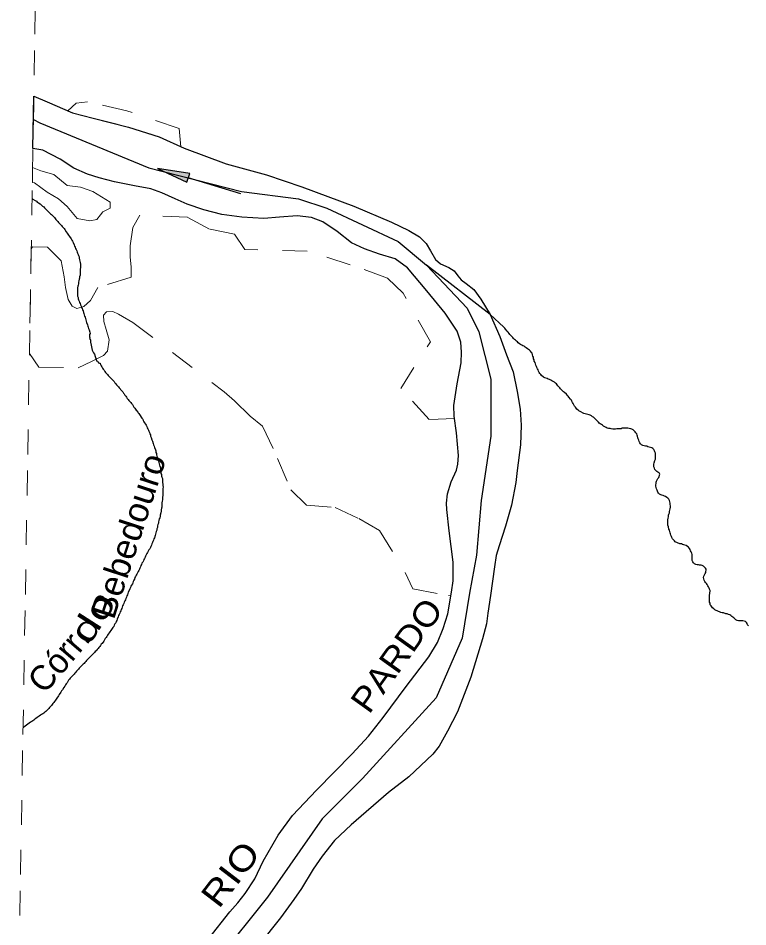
# Model space of a CAD drawing. Extents: x 785.9 to 812.4, y 7674.9 to 7703.1.
# Drawn here: x 786.199 to 789.145, y 7693.236 to 7696.903 of the extents above; entities that cross this region are included whole.
import ezdxf
from ezdxf.enums import TextEntityAlignment as Align

# ---------------------------------------------------------------- set-up
doc = ezdxf.new("R2010")
doc.units = 0
doc.header["$LTSCALE"] = 0.04
doc.linetypes.add('SHORT_DASHED', pattern=[2.7, 1.5, -1.2])
for name, color, linetype, lineweight in [('10', 7, 'Continuous', 25), ('2', 7, 'Continuous', 25), ('21', 7, 'SHORT_DASHED', 13), ('53', 7, 'SHORT_DASHED', 13), ('55', 7, 'Continuous', 25), ('7', 7, 'Continuous', 25)]:
    doc.layers.add(name, color=color, linetype=linetype, lineweight=lineweight)
doc.layers.add('61', color=7, linetype='Continuous')

msp = doc.modelspace()

# ---------------------------------------------------------------- hatches: boundary and pattern name
at = {"layer": '10'}
msp.add_hatch(color=256, dxfattribs=at).paths.add_polyline_path([(786.7608, 7696.2965), (786.8803, 7696.241), (786.8911, 7696.2763)])

# ---------------------------------------------------------------- linework, layer by layer
msp.add_line((787.0983, 7696.1942), (786.8857, 7696.2586), dxfattribs=at)
msp.add_lwpolyline([(786.7608, 7696.2965), (786.8803, 7696.241), (786.8911, 7696.2763)], close=True, dxfattribs=at)
at = {"layer": '2'}
for points in [[(787.4871, 7696.0426), (787.4289, 7696.0814), (787.3826, 7696.0986), (787.3255, 7696.1062), (787.2533, 7696.1008), (787.1908, 7696.0943), (787.1014, 7696.1008), (787.0206, 7696.1116), (786.9484, 7696.1299), (786.8805, 7696.1525), (786.832, 7696.1741), (786.7792, 7696.1978), (786.734, 7696.214), (786.6683, 7696.2269), (786.5875, 7696.2431), (786.525, 7696.2592), (786.4787, 7696.2732), (786.4237, 7696.298), (786.3677, 7696.3346), (786.2988, 7696.3702), (786.2583, 7696.3768), (786.2619, 7696.5891)], [(786.2619, 7696.5891), (786.3157, 7696.5656), (786.4181, 7696.5214), (786.501, 7696.4999), (786.6443, 7696.4633), (786.7682, 7696.4245), (786.8684, 7696.3781), (787.0386, 7696.3156), (787.2013, 7696.2704), (787.3445, 7696.223), (787.5546, 7696.1443), (787.7055, 7696.0807), (787.7766, 7696.0462), (787.8197, 7696.0215), (787.8455, 7695.9945), (787.8638, 7695.9643), (787.8843, 7695.9288), (787.9037, 7695.9115), (787.9382, 7695.8975), (787.9586, 7695.8835), (787.9737, 7695.8641), (787.9877, 7695.8469), (788.0071, 7695.8329), (788.0384, 7695.8081), (788.0674, 7695.7693), (788.1051, 7695.7068), (788.1439, 7695.6184), (788.1698, 7695.5452), (788.1967, 7695.4762), (788.214, 7695.3965), (788.2258, 7695.3253), (788.229, 7695.2607), (788.2269, 7695.181), (788.2129, 7695.0775), (788.2075, 7695.029), (788.1903, 7694.9385), (788.1666, 7694.8534), (788.1407, 7694.7737), (788.1288, 7694.7349), (788.1224, 7694.6885), (788.1062, 7694.5732), (788.0954, 7694.5021), (788.089, 7694.459), (788.0739, 7694.3987), (788.0265, 7694.2435), (787.9727, 7694.1045), (787.9328, 7694.0259), (787.8984, 7693.9655), (787.8725, 7693.9332), (787.7766, 7693.8416), (787.6936, 7693.778), (787.5428, 7693.6476), (787.476, 7693.5852), (787.4265, 7693.5216), (787.3898, 7693.4688), (787.3424, 7693.3912), (787.3123, 7693.347), (787.2573, 7693.2727), (787.1733, 7693.166)], [(786.9688, 7693.1893), (787.0529, 7693.2971), (787.0852, 7693.3337), (787.1153, 7693.3703), (787.1541, 7693.4296), (787.1875, 7693.5007), (787.2478, 7693.6063), (787.306, 7693.685), (787.4029, 7693.7874), (787.5473, 7693.9339), (787.6131, 7694.0061), (787.6723, 7694.0815), (787.765, 7694.2065), (787.8565, 7694.3261), (787.8921, 7694.3832), (787.9147, 7694.4403), (787.933, 7694.4996), (787.9481, 7694.5869), (787.9546, 7694.6321), (787.9546, 7694.7076), (787.9395, 7694.8347), (787.9298, 7694.9209), (787.9287, 7694.9467), (787.932, 7694.9834), (787.947, 7695.0319), (787.9686, 7695.0793), (787.974, 7695.104), (787.9772, 7695.1385), (787.9686, 7695.2301), (787.9589, 7695.297), (787.9579, 7695.3401), (787.9708, 7695.4273), (787.988, 7695.5125), (787.9891, 7695.5556), (787.9859, 7695.5954), (787.9718, 7695.6396), (787.9223, 7695.7129), (787.849, 7695.8034), (787.7704, 7695.896), (787.7208, 7695.9327), (787.6573, 7695.951), (787.5969, 7695.9725), (787.5442, 7695.9973), (787.4871, 7696.0426)]]:
    msp.add_lwpolyline(points, dxfattribs=at)
at = {"layer": '21'}
msp.add_line((786.2513, 7695.9719), (786.2441, 7695.5504), dxfattribs=at)
for points in [[(786.478, 7696.566), (786.4327, 7696.56), (786.3993, 7696.5295)], [(786.3993, 7696.5295), (786.4181, 7696.5214), (786.501, 7696.4999), (786.6443, 7696.4633), (786.7682, 7696.4245), (786.8549, 7696.3844)], [(786.8549, 7696.3844), (786.8486, 7696.4584), (786.637, 7696.5293), (786.478, 7696.566)], [(786.257, 7696.3011), (786.2565, 7696.2732), (786.2559, 7696.2402), (786.264, 7696.2388), (786.3157, 7696.2009)], [(786.3157, 7696.2009), (786.3619, 7696.1741), (786.397, 7696.1436), (786.4367, 7696.0955), (786.4875, 7696.0854), (786.5162, 7696.0909), (786.5309, 7696.1103), (786.5411, 7696.1223), (786.5697, 7696.1371), (786.5707, 7696.1612), (786.5005, 7696.2037), (786.4506, 7696.2212), (786.397, 7696.2286), (786.3425, 7696.2721), (786.2908, 7696.2878), (786.257, 7696.3011)], [(787.9602, 7695.2883), (787.8583, 7695.2835), (787.7432, 7695.4085), (787.8632, 7695.5973), (787.753, 7695.7933), (787.6893, 7695.8546), (787.5398, 7695.9085), (787.3659, 7695.9625), (787.1136, 7695.9698), (787.0719, 7696.0311), (786.9716, 7696.0523), (786.8825, 7696.0996), (786.6899, 7696.1077), (786.661, 7696.0579), (786.6514, 7695.9849), (786.6514, 7695.9383), (786.6546, 7695.8994), (786.6546, 7695.8577), (786.5206, 7695.8159), (786.5206, 7695.8159)], [(786.5206, 7695.8159), (786.4901, 7695.7645), (786.4644, 7695.7396), (786.4355, 7695.7316), (786.4162, 7695.7404), (786.4002, 7695.7677), (786.3898, 7695.8158), (786.3841, 7695.8592), (786.372, 7695.9238), (786.3167, 7695.979), (786.2566, 7695.9801), (786.2513, 7695.9719)], [(786.2441, 7695.5504), (786.2822, 7695.4948), (786.4403, 7695.4924), (786.4941, 7695.5181), (786.5438, 7695.5421), (786.5591, 7695.5598), (786.5655, 7695.6047), (786.5543, 7695.6473), (786.5446, 7695.6786), (786.5438, 7695.7043), (786.5551, 7695.7187), (786.5815, 7695.7195), (786.604, 7695.7083), (786.662, 7695.6746)], [(786.662, 7695.6746), (787.0303, 7695.396), (787.0723, 7695.3585), (787.136, 7695.2972), (787.1846, 7695.2563), (787.2463, 7695.1269), (787.2999, 7695.0003), (787.3633, 7694.9377), (787.4788, 7694.9281), (787.5741, 7694.8837), (787.6574, 7694.836), (787.7616, 7694.666), (787.7922, 7694.6007), (787.9358, 7694.5734), (787.9455, 7694.5719)]]:
    msp.add_lwpolyline(points, dxfattribs=at)
at = {"layer": '53'}
msp.add_lwpolyline([(786.1986, 7692.8823), (786.2082, 7693.4474), (786.2179, 7694.0126), (786.2276, 7694.5777), (786.2372, 7695.1429), (786.2468, 7695.708), (786.2565, 7696.2732), (786.2661, 7696.8383), (786.2758, 7697.4034), (786.2854, 7697.9686), (786.2951, 7698.5337), (786.3047, 7699.0989), (786.3143, 7699.664), (786.324, 7700.2291), (786.3336, 7700.7943), (786.3432, 7701.3594), (786.3528, 7701.9246), (786.3625, 7702.4897), (786.3721, 7703.0549)], dxfattribs=at)
at = {"layer": '55'}
for p, q in [((786.2603, 7696.4943), (786.2859, 7696.4815)), ((788.1051, 7695.7068), (787.8479, 7695.9062))]:
    msp.add_line(p, q, dxfattribs=at)
msp.add_lwpolyline([(786.2859, 7696.4815), (786.7267, 7696.2993), (787.1005, 7696.2034), (787.3305, 7696.1747), (787.4455, 7696.1363), (787.5892, 7696.0692), (787.7329, 7696.0021), (787.8479, 7695.9062), (788.0109, 7695.7336), (788.0588, 7695.6377), (788.1067, 7695.4459), (788.1067, 7695.2158), (788.0683, 7694.9569), (788.0492, 7694.7363), (788.0204, 7694.5829), (787.9917, 7694.4007), (787.8863, 7694.161), (787.5892, 7693.835), (787.4263, 7693.672), (787.2059, 7693.3555), (787.0046, 7693.1062)], dxfattribs=at)
at = {"layer": '7'}
for points in [[(786.2548, 7696.1752), (786.2582, 7696.1731), (786.2671, 7696.1674), (786.272, 7696.1642), (786.276, 7696.1609), (786.2801, 7696.1577), (786.2873, 7696.1536), (786.2971, 7696.1447), (786.3019, 7696.1415), (786.3051, 7696.1375), (786.3084, 7696.1334), (786.3132, 7696.1302), (786.3173, 7696.1261), (786.3213, 7696.1221), (786.3294, 7696.114), (786.3335, 7696.1108), (786.3367, 7696.1067), (786.3448, 7696.0986), (786.348, 7696.0946), (786.3513, 7696.0905), (786.3545, 7696.0865), (786.3585, 7696.0833), (786.3618, 7696.0792), (786.3699, 7696.0711), (786.3731, 7696.0671), (786.3764, 7696.063), (786.3844, 7696.0549), (786.3877, 7696.0501), (786.3925, 7696.0404), (786.3958, 7696.0355), (786.4022, 7696.0274), (786.4055, 7696.0226), (786.412, 7696.0129), (786.4152, 7696.008), (786.4176, 7696.0031), (786.4209, 7695.9983), (786.4241, 7695.9886), (786.4265, 7695.9837), (786.4289, 7695.9789), (786.4306, 7695.974), (786.433, 7695.9692), (786.4354, 7695.9643), (786.437, 7695.9595), (786.4387, 7695.9546), (786.4403, 7695.9497), (786.4427, 7695.9449), (786.4443, 7695.94), (786.4451, 7695.9344), (786.4467, 7695.9287), (786.4476, 7695.923), (786.4492, 7695.9174), (786.45, 7695.9109), (786.45, 7695.8996), (786.4492, 7695.8883), (786.4492, 7695.8713), (786.4484, 7695.8656), (786.4467, 7695.8599), (786.4459, 7695.8543), (786.4443, 7695.8494), (786.4435, 7695.8437), (786.4427, 7695.8381), (786.4419, 7695.8316), (786.4411, 7695.8259), (786.4395, 7695.8211), (786.4387, 7695.8154), (786.4378, 7695.8098), (786.4378, 7695.7871), (786.4387, 7695.7814), (786.4403, 7695.7766), (786.4411, 7695.7709), (786.4427, 7695.7661), (786.4451, 7695.7612), (786.4467, 7695.7564), (786.4492, 7695.7515), (786.4508, 7695.7467), (786.4524, 7695.741), (786.4548, 7695.7361), (786.4565, 7695.7313), (786.4589, 7695.7264), (786.4613, 7695.7216), (786.4621, 7695.7159), (786.4637, 7695.711), (786.4654, 7695.7062), (786.467, 7695.7013), (786.4686, 7695.6965), (786.4702, 7695.6908), (786.4718, 7695.686), (786.4734, 7695.6811), (786.4751, 7695.6754), (786.4783, 7695.6657), (786.4799, 7695.6609), (786.4815, 7695.656), (786.4832, 7695.6512), (786.4848, 7695.6455), (786.488, 7695.6358), (786.4896, 7695.6309), (786.4866, 7695.6266), (786.4866, 7695.6215)], [(788.455, 7695.3251), (788.4518, 7695.3291), (788.4486, 7695.3332), (788.4453, 7695.338), (788.4421, 7695.3429), (788.4397, 7695.3477), (788.4364, 7695.3526), (788.4348, 7695.3575), (788.4324, 7695.3623), (788.4291, 7695.3664), (788.4227, 7695.3744), (788.4194, 7695.3785), (788.4154, 7695.3817), (788.4122, 7695.3858), (788.4041, 7695.3922), (788.4, 7695.3955), (788.396, 7695.3987), (788.3927, 7695.4028), (788.3887, 7695.4068), (788.3855, 7695.4109), (788.3814, 7695.4149), (788.3782, 7695.4189), (788.3717, 7695.427), (788.3677, 7695.4303), (788.3636, 7695.4343), (788.3539, 7695.4392), (788.349, 7695.4424), (788.3442, 7695.4448), (788.3393, 7695.4465), (788.3345, 7695.4489), (788.3248, 7695.4521), (788.3199, 7695.4545), (788.3118, 7695.461), (788.3086, 7695.4659), (788.3053, 7695.4699), (788.3021, 7695.474), (788.2997, 7695.4788), (788.2981, 7695.4837), (788.2956, 7695.4885), (788.2932, 7695.4934), (788.2916, 7695.4982), (788.2892, 7695.5031), (788.2875, 7695.508), (788.2859, 7695.5136), (788.2827, 7695.5185), (788.2819, 7695.5241), (788.2795, 7695.529), (788.2795, 7695.5347), (788.277, 7695.5395), (788.2754, 7695.5452), (788.2738, 7695.5508), (788.2706, 7695.5549), (788.2673, 7695.5589), (788.2633, 7695.563), (788.2592, 7695.5662), (788.2552, 7695.5694), (788.2503, 7695.5727), (788.2463, 7695.5759), (788.2414, 7695.5792), (788.2366, 7695.5816), (788.2317, 7695.584), (788.2269, 7695.5864), (788.2228, 7695.5897), (788.218, 7695.5929), (788.2147, 7695.597), (788.2107, 7695.6002), (788.2066, 7695.6034), (788.2026, 7695.6067), (788.1985, 7695.6107), (788.1953, 7695.6148), (788.1913, 7695.618), (788.188, 7695.622), (788.184, 7695.6261), (788.1807, 7695.6309), (788.1775, 7695.6358), (788.1735, 7695.6398), (788.167, 7695.6479), (788.1637, 7695.652), (788.1597, 7695.656), (788.1051, 7695.7068)], [(786.4866, 7695.6215), (786.4866, 7695.6169), (786.4881, 7695.6134), (786.4866, 7695.6098), (786.4897, 7695.6073), (786.4912, 7695.6042), (786.4912, 7695.5956), (786.4927, 7695.5833), (786.4973, 7695.5635), (786.5029, 7695.5533), (786.5065, 7695.5472), (786.5095, 7695.5375), (786.5131, 7695.5253), (786.5161, 7695.5197), (786.5187, 7695.5187), (786.5207, 7695.5166), (786.5222, 7695.5161), (786.5227, 7695.5126), (786.5273, 7695.511), (786.5293, 7695.5104), (786.5309, 7695.5055), (786.5333, 7695.5007), (786.5358, 7695.4958), (786.539, 7695.491), (786.5422, 7695.4869), (786.5455, 7695.4829), (786.5487, 7695.478), (786.5519, 7695.4732), (786.5552, 7695.4691), (786.5592, 7695.4651), (786.5625, 7695.461), (786.5665, 7695.457), (786.5697, 7695.4529), (786.5778, 7695.4448), (786.5819, 7695.4408), (786.5859, 7695.4367), (786.5892, 7695.4319), (786.5924, 7695.4278), (786.5956, 7695.4238), (786.5997, 7695.4198), (786.6037, 7695.4157), (786.607, 7695.4109), (786.6167, 7695.3987), (786.6207, 7695.3947), (786.6239, 7695.3906), (786.6272, 7695.3866), (786.6288, 7695.3817), (786.6328, 7695.3777), (786.6361, 7695.3736), (786.6385, 7695.3688), (786.6426, 7695.3647), (786.6458, 7695.3607), (786.649, 7695.3558), (786.6531, 7695.3518), (786.6563, 7695.3477), (786.6596, 7695.3437), (786.6628, 7695.3388), (786.666, 7695.334), (786.6693, 7695.3291), (786.6757, 7695.321), (786.6798, 7695.317), (786.6822, 7695.3121), (786.6854, 7695.3081), (786.6887, 7695.304), (786.6984, 7695.2895), (786.7016, 7695.2846), (786.7032, 7695.279), (786.7065, 7695.2749), (786.7089, 7695.2701), (786.7121, 7695.2652), (786.7154, 7695.2604), (786.7178, 7695.2555), (786.7194, 7695.2506), (786.7219, 7695.2458), (786.7243, 7695.2409), (786.7267, 7695.2361), (786.7291, 7695.2312), (786.7308, 7695.2264), (786.7324, 7695.2215), (786.7332, 7695.2159), (786.7356, 7695.211), (786.7388, 7695.2013), (786.7405, 7695.1964), (786.7437, 7695.1867), (786.7453, 7695.1811), (786.7477, 7695.1762), (786.7494, 7695.1713), (786.7526, 7695.1616), (786.7542, 7695.1568), (786.7542, 7695.1511), (786.7566, 7695.1463), (786.7575, 7695.1406), (786.7591, 7695.1357), (786.7607, 7695.1301), (786.7623, 7695.1252), (786.7655, 7695.1155), (786.7664, 7695.1099), (786.768, 7695.105), (786.7696, 7695.0993), (786.7712, 7695.0945), (786.7728, 7695.0896)], [(788.8216, 7694.9658), (788.8175, 7694.9691), (788.8127, 7694.9723), (788.8078, 7694.9739), (788.803, 7694.9763), (788.7981, 7694.978), (788.7933, 7694.9796), (788.7884, 7694.9828), (788.7844, 7694.9861), (788.7811, 7694.9901), (788.7787, 7694.999), (788.7763, 7695.0039), (788.7747, 7695.0087), (788.773, 7695.0144), (788.773, 7695.02), (788.7747, 7695.0249), (788.7747, 7695.0306), (788.7763, 7695.0354), (788.7787, 7695.0403), (788.7819, 7695.0451), (788.786, 7695.0492), (788.79, 7695.0629), (788.7868, 7695.0678), (788.7819, 7695.071), (788.7779, 7695.0743), (788.7738, 7695.0783), (788.7698, 7695.0823), (788.7674, 7695.0872), (788.7658, 7695.0921), (788.7649, 7695.0977), (788.7649, 7695.1034), (788.7666, 7695.109), (788.7698, 7695.1188), (788.7714, 7695.1236), (788.7722, 7695.1366), (788.7714, 7695.1422), (788.7714, 7695.1479), (788.769, 7695.1527), (788.7674, 7695.1576), (788.7649, 7695.1624), (788.7617, 7695.1665), (788.7568, 7695.1689), (788.752, 7695.1705), (788.7471, 7695.1722), (788.7415, 7695.1738), (788.7366, 7695.1754), (788.731, 7695.1762), (788.7261, 7695.1778), (788.7204, 7695.1786), (788.7156, 7695.1819), (788.7115, 7695.1851), (788.7083, 7695.19), (788.7067, 7695.1948), (788.7043, 7695.1997), (788.7026, 7695.2053), (788.701, 7695.2102), (788.6994, 7695.2159), (788.6978, 7695.2207), (788.6962, 7695.2256), (788.6929, 7695.2304), (788.6897, 7695.2345), (788.6856, 7695.2385), (788.6816, 7695.2417), (788.6767, 7695.2442), (788.6719, 7695.2458), (788.6662, 7695.2474), (788.6606, 7695.2482), (788.6379, 7695.2482), (788.6331, 7695.2466), (788.6274, 7695.2466), (788.6217, 7695.2458), (788.6161, 7695.2458), (788.6104, 7695.245), (788.5991, 7695.245), (788.5934, 7695.2458), (788.5885, 7695.2474), (788.5829, 7695.2474), (788.5772, 7695.249), (788.5724, 7695.2515), (788.5675, 7695.2547), (788.5627, 7695.2571), (788.5578, 7695.2604), (788.5538, 7695.2636), (788.5489, 7695.266), (788.5449, 7695.2693), (788.5416, 7695.2733), (788.5376, 7695.2773), (788.5343, 7695.2814), (788.5262, 7695.2895), (788.5222, 7695.2927), (788.5173, 7695.2951), (788.5133, 7695.2984), (788.5084, 7695.3008), (788.5036, 7695.3024), (788.4939, 7695.3057), (788.4882, 7695.3065), (788.4826, 7695.3081), (788.468, 7695.3154), (788.4631, 7695.3186), (788.4591, 7695.3219), (788.455, 7695.3251)], [(786.7728, 7695.0896), (786.7736, 7695.0791), (786.7753, 7695.0662), (786.7769, 7695.0613), (786.7777, 7695.0556), (786.7793, 7695.0508), (786.7809, 7695.0459), (786.7809, 7695.0346), (786.7817, 7695.0289), (786.7833, 7695.0233), (786.7833, 7695.0168), (786.7842, 7695.0111), (786.7833, 7695.0047), (786.7833, 7694.9933), (786.7825, 7694.9877), (786.7825, 7694.9763), (786.7817, 7694.9707), (786.7817, 7694.965), (786.7809, 7694.9594), (786.7801, 7694.9537), (786.7793, 7694.948), (786.7793, 7694.9359), (786.7785, 7694.9302), (786.7769, 7694.9254), (786.7761, 7694.9189), (786.7761, 7694.9132), (786.7753, 7694.9076), (786.772, 7694.8979), (786.772, 7694.8922), (786.7704, 7694.8873), (786.768, 7694.8825), (786.7672, 7694.876), (786.7655, 7694.8712), (786.7647, 7694.8655), (786.7623, 7694.8598), (786.7615, 7694.8542), (786.7607, 7694.8477), (786.7591, 7694.842), (786.7583, 7694.8364), (786.7558, 7694.8315), (786.755, 7694.8258), (786.7534, 7694.821), (786.7518, 7694.8161), (786.7486, 7694.8064), (786.7469, 7694.8016), (786.7445, 7694.7967), (786.7421, 7694.7919), (786.7405, 7694.787), (786.7388, 7694.7813), (786.7364, 7694.7765), (786.7348, 7694.7716), (786.7324, 7694.7668), (786.7299, 7694.7619), (786.7267, 7694.7571), (786.7235, 7694.7522), (786.721, 7694.7474), (786.7186, 7694.7425), (786.7154, 7694.7376), (786.713, 7694.7328), (786.7113, 7694.7279), (786.7089, 7694.7231), (786.7057, 7694.7182), (786.7041, 7694.7134), (786.7016, 7694.7085), (786.6984, 7694.7037), (786.6968, 7694.6988), (786.6943, 7694.694), (786.6919, 7694.6891), (786.6895, 7694.6842), (786.6879, 7694.6794), (786.6854, 7694.6745), (786.683, 7694.6697), (786.6798, 7694.6648), (786.6782, 7694.66), (786.6749, 7694.6551), (786.6725, 7694.6503), (786.6693, 7694.6454), (786.6685, 7694.6397), (786.666, 7694.6349), (786.6628, 7694.63), (786.6612, 7694.6252), (786.6596, 7694.6203), (786.6563, 7694.6155), (786.6539, 7694.6106), (786.6523, 7694.6058), (786.6498, 7694.6009), (786.6482, 7694.596), (786.6434, 7694.5863), (786.6401, 7694.5766), (786.6377, 7694.5718), (786.6361, 7694.5661), (786.6337, 7694.5613), (786.632, 7694.5564), (786.6296, 7694.5515), (786.6264, 7694.5467), (786.6256, 7694.541), (786.6231, 7694.5362), (786.6199, 7694.5313), (786.6167, 7694.5216), (786.6142, 7694.5168), (786.6126, 7694.5119)], [(789.0765, 7694.4925), (789.0716, 7694.4957), (789.0668, 7694.4973), (789.0619, 7694.499), (789.0562, 7694.4998), (789.0465, 7694.503), (789.0409, 7694.5038), (789.036, 7694.5054), (789.0311, 7694.507), (789.0263, 7694.5087), (789.0214, 7694.5111), (789.0166, 7694.5127), (789.0117, 7694.5159), (789.0069, 7694.5192), (789.0028, 7694.5232), (788.9996, 7694.5273), (788.9964, 7694.5313), (788.9931, 7694.5362), (788.9923, 7694.5418), (788.9899, 7694.5467), (788.9899, 7694.5637), (788.9907, 7694.5693), (788.9907, 7694.575), (788.9915, 7694.5815), (788.9923, 7694.5936), (788.9907, 7694.5985), (788.9891, 7694.6033), (788.9866, 7694.6082), (788.9834, 7694.613), (788.981, 7694.6179), (788.9777, 7694.6219), (788.9745, 7694.626), (788.9713, 7694.63), (788.968, 7694.6349), (788.9672, 7694.6406), (788.9664, 7694.6462), (788.9672, 7694.6519), (788.9705, 7694.6567), (788.9729, 7694.6616), (788.9753, 7694.6664), (788.9769, 7694.6794), (788.9737, 7694.6842), (788.9705, 7694.6883), (788.9656, 7694.6915), (788.9608, 7694.694), (788.9559, 7694.6956), (788.9502, 7694.6956), (788.9454, 7694.6972), (788.9397, 7694.6972), (788.9349, 7694.6988), (788.93, 7694.7012), (788.926, 7694.7053), (788.9227, 7694.7093), (788.9203, 7694.7142), (788.9203, 7694.7393), (788.9187, 7694.7441), (788.9163, 7694.749), (788.9138, 7694.7538), (788.9114, 7694.7587), (788.909, 7694.7635), (788.9057, 7694.7684), (788.9009, 7694.7716), (788.896, 7694.7749), (788.8863, 7694.7781), (788.8815, 7694.7797), (788.8766, 7694.7813), (788.8709, 7694.7822), (788.8612, 7694.7854), (788.8515, 7694.7902), (788.8483, 7694.7943), (788.8442, 7694.7983), (788.841, 7694.8024), (788.8378, 7694.8072), (788.8361, 7694.8121), (788.8345, 7694.8169), (788.8329, 7694.8218), (788.8313, 7694.8267), (788.8297, 7694.8315), (788.8281, 7694.8364), (788.8256, 7694.8412), (788.824, 7694.8509), (788.8224, 7694.8566), (788.8216, 7694.8623), (788.8216, 7694.8736), (788.8224, 7694.8792), (788.8232, 7694.8849), (788.824, 7694.8906), (788.8248, 7694.897), (788.8264, 7694.9019), (788.8281, 7694.9068), (788.8281, 7694.9124), (788.8305, 7694.9173), (788.8313, 7694.9229), (788.8321, 7694.9294), (788.8321, 7694.9351), (788.8313, 7694.9407), (788.8313, 7694.9464), (788.8297, 7694.9513), (788.8289, 7694.9569), (788.8256, 7694.9618), (788.8216, 7694.9658)], [(786.6126, 7694.5119), (786.6102, 7694.507), (786.6086, 7694.5022), (786.6061, 7694.4973), (786.6037, 7694.4925), (786.6021, 7694.4876), (786.5989, 7694.4779), (786.5964, 7694.4731), (786.594, 7694.4682), (786.5924, 7694.4633), (786.5892, 7694.4585), (786.5867, 7694.4536), (786.5843, 7694.4488), (786.5811, 7694.4447), (786.5786, 7694.4399), (786.5754, 7694.4358), (786.5722, 7694.4318), (786.5689, 7694.4269), (786.5657, 7694.4221), (786.5625, 7694.4172), (786.5592, 7694.4132), (786.5568, 7694.4083), (786.5536, 7694.4035), (786.5503, 7694.3994), (786.5471, 7694.3946), (786.5447, 7694.3897), (786.5382, 7694.38), (786.5341, 7694.3768), (786.5309, 7694.3719), (786.5277, 7694.3671), (786.5244, 7694.363), (786.5212, 7694.359), (786.5171, 7694.3549), (786.5139, 7694.3501), (786.5099, 7694.3468), (786.5066, 7694.3428), (786.5034, 7694.3387), (786.4993, 7694.3347), (786.4945, 7694.3315), (786.4904, 7694.3274), (786.4872, 7694.3234), (786.4832, 7694.3193), (786.4791, 7694.3153), (786.4751, 7694.3112), (786.4718, 7694.3072), (786.4678, 7694.3031), (786.4645, 7694.2991), (786.4605, 7694.2959), (786.4573, 7694.2918), (786.4532, 7694.2878), (786.4492, 7694.2845), (786.4451, 7694.2805), (786.4419, 7694.2764), (786.4387, 7694.2724), (786.4346, 7694.2683), (786.4314, 7694.2643), (786.4273, 7694.2603), (786.4241, 7694.2562), (786.4209, 7694.2514), (786.4128, 7694.2433), (786.4087, 7694.24), (786.4055, 7694.2352), (786.4022, 7694.2311), (786.3958, 7694.2214), (786.3925, 7694.2174), (786.3901, 7694.2125), (786.3869, 7694.2077), (786.3836, 7694.2028), (786.3772, 7694.1931), (786.3739, 7694.1882), (786.3707, 7694.1834), (786.3642, 7694.1737), (786.3618, 7694.1688), (786.3553, 7694.1591), (786.3521, 7694.1551), (786.3488, 7694.151), (786.3456, 7694.1462), (786.3424, 7694.1421), (786.3391, 7694.1381), (786.3327, 7694.13), (786.3294, 7694.1259), (786.3254, 7694.1219), (786.3221, 7694.1178), (786.31, 7694.1057), (786.306, 7694.1025), (786.3019, 7694.0992), (786.2979, 7694.096), (786.293, 7694.0928), (786.2882, 7694.0903), (786.2833, 7694.0871), (786.2752, 7694.0806), (786.2704, 7694.0774), (786.2663, 7694.0742), (786.2615, 7694.0709), (786.2574, 7694.0677), (786.2534, 7694.0644), (786.2485, 7694.062), (786.2437, 7694.0588), (786.2275, 7694.0466), (786.2197, 7694.0408), (786.2184, 7694.0399)], [(789.1469, 7694.4504), (789.1436, 7694.4553), (789.142, 7694.4601), (789.1396, 7694.465), (789.1355, 7694.4682), (789.1307, 7694.4698), (789.125, 7694.4706), (789.1193, 7694.4706), (789.1129, 7694.4714), (789.1072, 7694.4714), (789.1015, 7694.4731), (789.0967, 7694.4755), (789.0926, 7694.4795), (789.0886, 7694.4828), (789.0846, 7694.486), (789.0805, 7694.4892), (789.0765, 7694.4925)]]:
    msp.add_lwpolyline(points, dxfattribs=at)

# ---------------------------------------------------------------- texts
at = {"layer": '61'}
for s, rotation, width, p in [('Bebedouro', 71.931, 1.05, (786.6911, 7694.7987)), ('do', 57.278, 1.4, (786.5414, 7694.457)), ('PARDO', 54.417, 1.1, (787.7677, 7694.3032)), ('RIO', 52.587, 1.2, (787.0955, 7693.4189))]:
    msp.add_text(s, height=0.1, rotation=rotation, dxfattribs=dict(at, width=width)).set_placement(p, align=Align.CENTER)
msp.add_text('Córr.', height=0.1, rotation=49.569, dxfattribs=at).set_placement((786.4009, 7694.2849), align=Align.CENTER)

doc.saveas('drawing.dxf')
